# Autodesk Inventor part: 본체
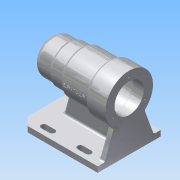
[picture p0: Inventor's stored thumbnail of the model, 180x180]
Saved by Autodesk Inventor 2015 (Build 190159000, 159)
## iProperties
Created: 2017-09
Part Number: 본체
Material: 알루미늄 6061
Document SubType Name: Modeling
Designer: Administrator
Density: 2.7 g/cm^3
Appearance: 알루미늄 - 평지
Author: Administrator
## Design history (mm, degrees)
sketch "스케치1"
  geometry: L1 (-133.636, 0)-(143, 0); L2 (112, 34)-(112, 0); L3 (112, 34)-(84, 34); L4 (84, 34)-(84, 30); L5 (84, 30)-(45, 30); L6 (45, 30)-(45, 27); L7 (45, 27)-(25, 27); L8 (0, 0)-(112, 0); L9 (25, 27)-(25, 25); L10 (25, 25)-(0, 25); L11 (0, 25)-(0, 0)
  constraints: 23 end point, 5 perpendicular, 3 horizontal, 3 vertical, 1 point on line
  dimensions: "d1" = 68 diameter of L3 L1; "d2" = 112 distance between parallel lines of L2 L11; "d3" = 60 diameter of L5 L1; "d4" = 54 diameter of L7 L1; "d5" = 50 diameter of L10 L1; "d6" = 84 distance between parallel lines of L4 L11; "d7" = 45 distance between parallel lines of L6 L11; "d8" = 25 distance between parallel lines of L9 L11
revolve "회전1" sketch "스케치1" stored, may be unused: angle "d9" = 90 deg
sketch "스케치2"
  geometry: L1 (0, -25)-(0, 25) reference; L2 (0, 25)-(25, 25) reference; L3 (25, 25)-(25, 27) reference; L4 (25, 27)-(45, 27) reference; L5 (45, 27)-(45, 30) reference; L6 (45, 30)-(84, 30) reference; L7 (84, 30)-(84, 34) reference; L8 (84, 34)-(112, 34) reference; L9 (112, 34)-(112, -34) reference; L10 (112, -34)-(84, -34) reference; L11 (84, -34)-(84, -30) reference; L12 (84, -30)-(45, -30) reference; L13 (45, -30)-(45, -27) reference; L14 (45, -27)-(25, -27) reference; L15 (25, -27)-(25, -25) reference; L16 (25, -25)-(0, -25) reference; L17 (-42, 0)-(152.04, 0); L18 (31, 17.5)-(31, 21); L19 (31, 21)-(43, 21); L20 (43, 21)-(43, 24); L21 (43, 24)-(97, 24); L22 (97, 24)-(97, 21); L23 (97, 21)-(112, 21); L24 (31, 17.5)-(13, 17.5); L25 (13, 17.5)-(13, 16); L26 (13, 16)-(9, 16); L27 (9, 16)-(9, 10.5); L28 (9, 10.5)-(6, 10.5); L29 (6, 10.5)-(6, 0); L30 (112, 21)-(112, 0); L31 (112, -34)-(112, 34) reference; L32 (6, 0)-(112, 0); 2 further points
  constraints: 30 end point, 9 perpendicular, 3 point on line, 3 vertical, 2 horizontal, 2 midpoint
  dimensions: "d10" = 42 diameter of L23 L17; "d11" = 15 distance of L22.end L23.end; "d12" = 48 diameter of L21 L17; "d13" = 54 distance of L20.end L21.end; "d14" = 42 diameter of L19 L17; "d15" = 12 distance between parallel lines of L20 L18; "d16" = 35 diameter of L24 L17; "d17" = 18 distance of L18.start L24.end; "d18" = 4 distance of L25.end L26.end; "d19" = 32 diameter of L26 L17; "d20" = 21 diameter of L28 L17; "d21" = 3 distance of L27.end L28.end
revolve "회전2" sketch "스케치2" stored, may be unused: angle "d22" = 90 deg
sketch "스케치3"
  geometry: L1 (-45, -62)-(45, -62); L2 (45, -62)-(45, -70); L3 (45, -70)-(-45, -70); L4 (-45, -70)-(-45, -62); C1 r 21 at (0, 0) reference; 1 further point
  constraints: 8 end point, 2 parallel, 1 horizontal, 1 midpoint, 1 perpendicular, 1 vertical alignment
  dimensions: "d23" = 8 distance between parallel lines of L3 L1; "d24" = 70 distance from line of L3 C1.centre; "d25" = 90 distance of L2.end L3.end
extrude "돌출1" join sketch "스케치3" distance "d26" = 112; taper "d27" = 0 deg
sketch "스케치4"
  geometry: L1 (21.067, -23.72)-(35.644, -63.77); L2 (35.644, -63.77)-(-35.644, -63.77); L3 (-35.644, -63.77)-(-21.067, -23.72); L4 (-21.067, -23.72)-(21.067, -23.72); L5 (-45, -62)-(45, -62) reference; L6 (-45, -70)-(-45, -62) reference; C1 r 21 at (0, 0) reference; 4 further points
  constraints: 8 end point, 4 point on line, 2 horizontal, 2 midpoint, 2 vertical alignment
  dimensions: "d28" = 110 deg angle of L5 L1; "d29" = 10 distance from line of L6 point (-35, -62)
extrude "돌출2" join sketch "스케치4" distance "d30" = 8; taper "d31" = 0 deg
sketch "스케치5"
  geometry: L1 (0, -25)-(0, 25) reference; L2 (0, 25)-(25, 25) reference; L3 (25, 25)-(25, 27) reference; L4 (25, 27)-(45, 27) reference; L5 (45, 27)-(45, 30) reference; L6 (45, 30)-(84, 30) reference; L7 (84, 30)-(84, 34) reference; L8 (84, 34)-(112, 34) reference; L9 (112, 34)-(112, 21) reference; L10 (112, 21)-(97, 21) reference; L11 (97, 21)-(97, 24) reference; L12 (97, 24)-(43, 24) reference; L13 (43, 24)-(43, 21) reference; L14 (43, 21)-(31, 21) reference; L15 (31, 21)-(31, 17.5) reference; L16 (31, 17.5)-(13, 17.5) reference; L17 (13, 17.5)-(13, 16) reference; L18 (13, 16)-(9, 16) reference; L19 (9, 16)-(9, 10.5) reference; L20 (9, 10.5)-(6, 10.5) reference; L21 (6, 10.5)-(6, -10.5) reference; L22 (6, -10.5)-(9, -10.5) reference; L23 (9, -10.5)-(9, -16) reference; L24 (9, -16)-(13, -16) reference; L25 (13, -16)-(13, -17.5) reference; L26 (13, -17.5)-(31, -17.5) reference; L27 (31, -17.5)-(31, -21) reference; L28 (31, -21)-(43, -21) reference; L29 (43, -21)-(43, -24) reference; L30 (43, -24)-(97, -24) reference; L31 (97, -24)-(97, -21) reference; L32 (97, -21)-(112, -21) reference; L33 (112, -21)-(112, -70) reference; L34 (112, -70)-(0, -70) reference; L35 (0, -70)-(0, -62) reference; L36 (0, -62)-(104, -62) reference; L37 (104, -62)-(104, -34) reference; L38 (104, -34)-(84, -34) reference; L39 (84, -34)-(84, -30) reference; L40 (84, -30)-(45, -30) reference; L41 (45, -30)-(45, -27) reference; L42 (45, -27)-(25, -27) reference; L43 (25, -27)-(25, -25) reference; L44 (25, -25)-(0, -25) reference; L45 (21.226, -64.887)-(31.878, -25.133); L46 (21.226, -64.887)-(107, -64.887); L47 (107, -64.887)-(107, -25.133); L48 (107, -25.133)-(31.878, -25.133); 2 further points
  constraints: 8 end point, 2 horizontal, 2 point on line, 1 vertical
  dimensions: "d32" = 105 deg angle of L45 L36; "d33" = 22 distance from line of L35 point (22, -62)
extrude "돌출3" join sketch "스케치5" stored distance "d34" = 8; taper "d35" = 0 deg
chamfer "모따기1" distance "d36" = 12; stored, may be unused: second distance "d37" = 2, angle "d38" = 45 deg
sketch "스케치6"
  geometry: L1 (0, 0)-(0, 10) reference; L2 (-88, 11)-(-76, 11); L3 (-88, 7)-(-76, 7); L4 (-76, 15)-(-88, 15); L5 (-36, 11)-(-24, 11); L6 (-36, 7)-(-24, 7); L7 (-24, 15)-(-36, 15); A1 r 4 centre (-88, 11) between (-88, 15) and (-88, 7); A2 r 4 centre (-76, 11) between (-76, 7) and (-76, 15); A3 r 4 centre (-36, 11) between (-36, 15) and (-36, 7); A4 r 4 centre (-24, 11) between (-24, 7) and (-24, 15); 3 further points
  constraints: 16 end point, 8 point on circle, 8 tangent, 4 centre point, 2 horizontal, 2 midpoint, 2 parallel, 1 horizontal alignment
  dimensions: "d39" = 4 radius of A1; "d40" = 12 distance of L2.start L2.end; "d41" = 34 distance from line of L2 point (-112, 45); "d42" = 12 distance of L5.start L5.end; "d43" = 4 radius of A3; "d44" = 24 distance from line of L1 L5.end; "d45" = 40 distance of L2.end L5.start
extrude "돌출4" cut sketch "스케치6" stored distance "d46" = 8; taper "d47" = 0 deg
fillet "모깎기1" dims "d48" = 9
fillet "모깎기2" dims "d49" = 3
fillet "모깎기3" dims "d50" = 0.3
fillet "모깎기4" dims "d51" = 3
fillet "모깎기5" dims "d52" = 3
sketch "스케치7"
  geometry: A1 r 34 centre (45, 70) between (66.9, 43.992) and (23.1, 43.992) reference; 1 further point
  constraints: 1 vertical alignment
  dimensions: "d53" = 26 distance of A1.centre point (45, 96)
hole "구멍1" sketch "스케치7" at (45, 96) diameter "d54" = 2.459; stored, may be unused: countersink angle "d58" = 90 deg, drill point angle "d60" = 118 deg; dims "d55" = 8, "d56" = 4, "d57" = 2, "d59" = 11
fillet "모깎기6" dims "d64" = 3
fillet "모깎기7" dims "d65" = 3
fillet "모깎기8" dims "d66" = 3
fillet "모깎기9" dims "d67" = 3
node "작업 평면1"
sketch "스케치8"
  geometry: L1 (47.196, -29.317)-(81, -29.317) reference; L2 (47.196, -29.317)-(47.196, -29.317) reference; L3 (81, -29.317)-(47.196, -29.317) reference; L4 (81, -29.317)-(81, -29.317) reference; L5 (86.657, -33.386)-(101, -33.386) reference; L6 (86.657, -33.386)-(86.657, -33.386) reference; L7 (101, -33.386)-(86.657, -33.386) reference; L8 (101, -28.328)-(101, -33.386) reference; L9 (112, -24.711)-(107, -24.711) reference; L10 (112, -24.711)-(112, -24.711) reference; L11 (107, -24.711)-(112, -24.711) reference; L12 (101, -33.386)-(101, -28.328) reference; L13 (112, -24.711)-(112, 34) reference; L14 (86.657, 34)-(112, 34) reference; L15 (47.196, 30)-(81, 30) reference; L16 (47.408, 2.402)-(80.592, 2.402); L17 (80.592, 2.402)-(80.592, -2.402); L18 (80.592, -2.402)-(47.408, -2.402); L19 (47.408, -2.402)-(47.408, 2.402); L20 (112, -70)-(12, -70) reference; 4 further points
  constraints: 2 midpoint, 1 horizontal alignment, 1 vertical alignment, 4 other
  dimensions: "d69" = 70 distance from line of point (64, 0) L20; "d70" = 48 distance from line of L13 point (64, 0)
feature "엠보싱1" sketch "스케치8" dims "d1" = 68, "d2" = 112, "d3" = 60, "d4" = 54, "d5" = 50, "d6" = 84, "d7" = 45, "d8" = 25, "d10" = 42, "d11" = 15, "d12" = 48, "d13" = 54, "d14" = 42, "d15" = 12, "d16" = 35, "d17" = 18, "d18" = 4, "d19" = 32, "d20" = 21, "d21" = 3, "d71" = 0.5, "d72" = 0
node "솔리드1"
mirror "대칭1"
pattern_circular "원형 패턴1" dims angle "d62" = 360 deg
node "투영된 루프1"
node "투영된 루프2"
node "절단 모서리 투영1"
node "절단 모서리 투영2"
other parameters: "d68" = 39.5
